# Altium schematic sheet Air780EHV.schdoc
size 373 x 116 mm
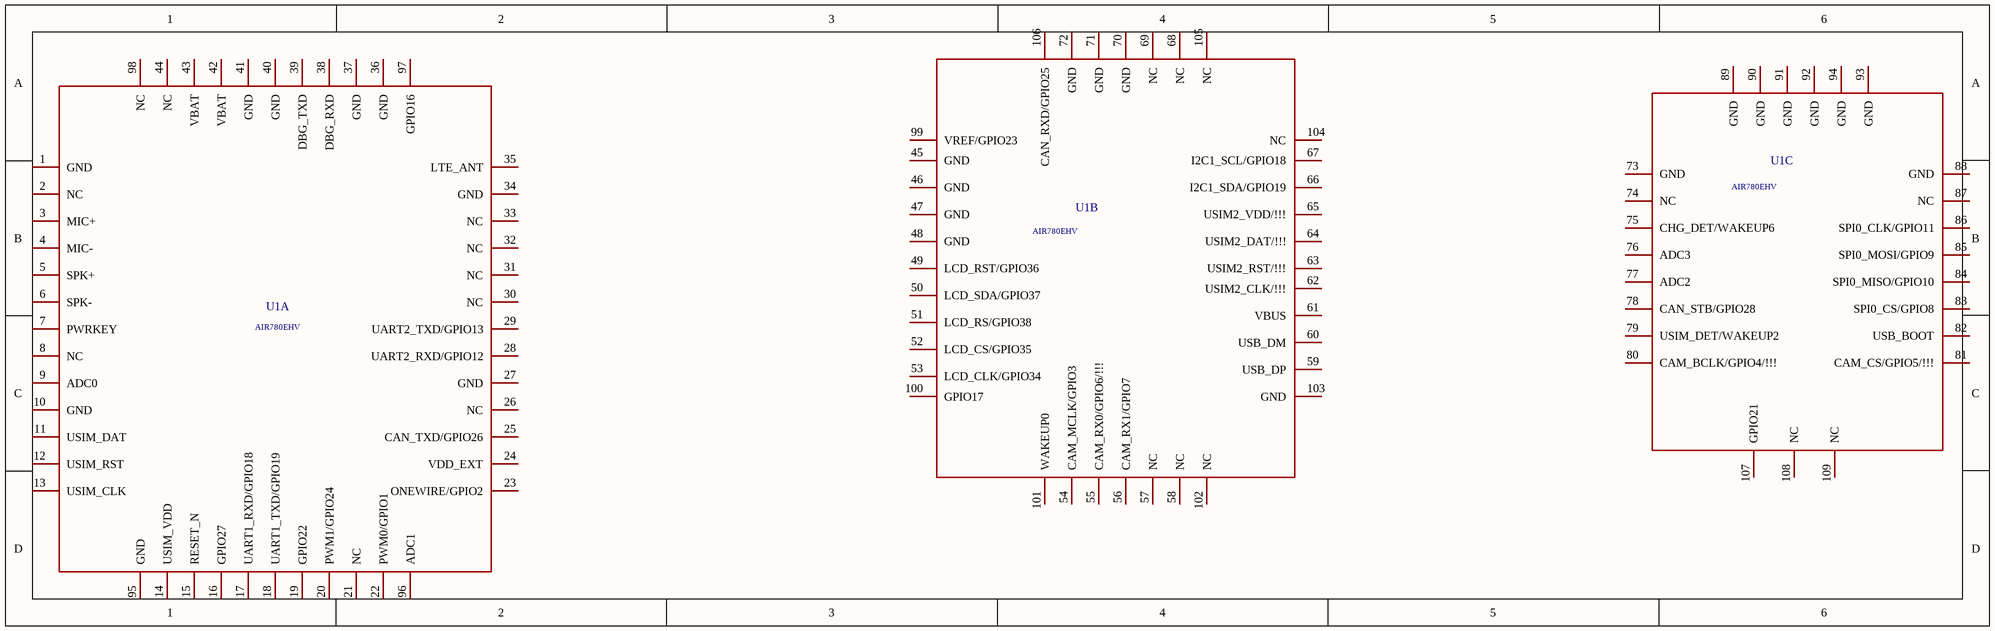
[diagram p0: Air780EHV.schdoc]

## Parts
U1  AIR780EHV  (parts A,B,C of 3)

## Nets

Not connected (* = marked no-connect by the designer): U1 1(GND) 2(NC) 3(MIC+) 4(MIC-) 5(SPK+) 6(SPK-) 7(PWRKEY) 8(NC) 9(ADC0) 10(GND) 11(USIM_DAT) 12(USIM_RST) 13(USIM_CLK) 14(USIM_VDD) 15(RESET_N) 16(GPIO27) 17(UART1_RXD/GPIO18) 18(UART1_TXD/GPIO19) 19(GPIO22) 20(PWM1/GPIO24) 21(NC) 22(PWM0/GPIO1) 23(ONEWIRE/GPIO2) 24(VDD_EXT) 25(CAN_TXD/GPIO26) 26(NC) 27(GND) 28(UART2_RXD/GPIO12) 29(UART2_TXD/GPIO13) 30(NC) 31(NC) 32(NC) 33(NC) 34(GND) 35(LTE_ANT) 36(GND) 37(GND) 38(DBG_RXD) 39(DBG_TXD) 40(GND) 41(GND) 42(VBAT) 43(VBAT) 44(NC) 45(GND) 46(GND) 47(GND) 48(GND) 49(LCD_RST/GPIO36) 50(LCD_SDA/GPIO37) 51(LCD_RS/GPIO38) 52(LCD_CS/GPIO35) 53(LCD_CLK/GPIO34) 54(CAM_MCLK/GPIO3) 55(CAM_RX0/GPIO6/!!!) 56(CAM_RX1/GPIO7) 57(NC) 58(NC) 59(USB_DP) 60(USB_DM) 61(VBUS) 62(USIM2_CLK/!!!) 63(USIM2_RST/!!!) 64(USIM2_DAT/!!!) 65(USIM2_VDD/!!!) 66(I2C1_SDA/GPIO19) 67(I2C1_SCL/GPIO18) 68(NC) 69(NC) 70(GND) 71(GND) 72(GND) 73(GND) 74(NC) 75(CHG_DET/WAKEUP6) 76(ADC3) 77(ADC2) 78(CAN_STB/GPIO28) 79(USIM_DET/WAKEUP2) 80(CAM_BCLK/GPIO4/!!!) 81(CAM_CS/GPIO5/!!!) 82(USB_BOOT) 83(SPI0_CS/GPIO8) 84(SPI0_MISO/GPIO10) 85(SPI0_MOSI/GPIO9) 86(SPI0_CLK/GPIO11) 87(NC) 88(GND) 89(GND) 90(GND) 91(GND) 92(GND) 93(GND) 94(GND) 95(GND) 96(ADC1) 97(GPIO16) 98(NC) 99(VREF/GPIO23) 100(GPIO17) 101(WAKEUP0) 102(NC) 103(GND) 104(NC) 105(NC) 106(CAN_RXD/GPIO25) 107(GPIO21) 108(NC) 109(NC)

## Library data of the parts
U1 = AIR780EHV: Add into BOM: yes; Origin Footprint: LGA-109_L17.7-W15.8-AIR780E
